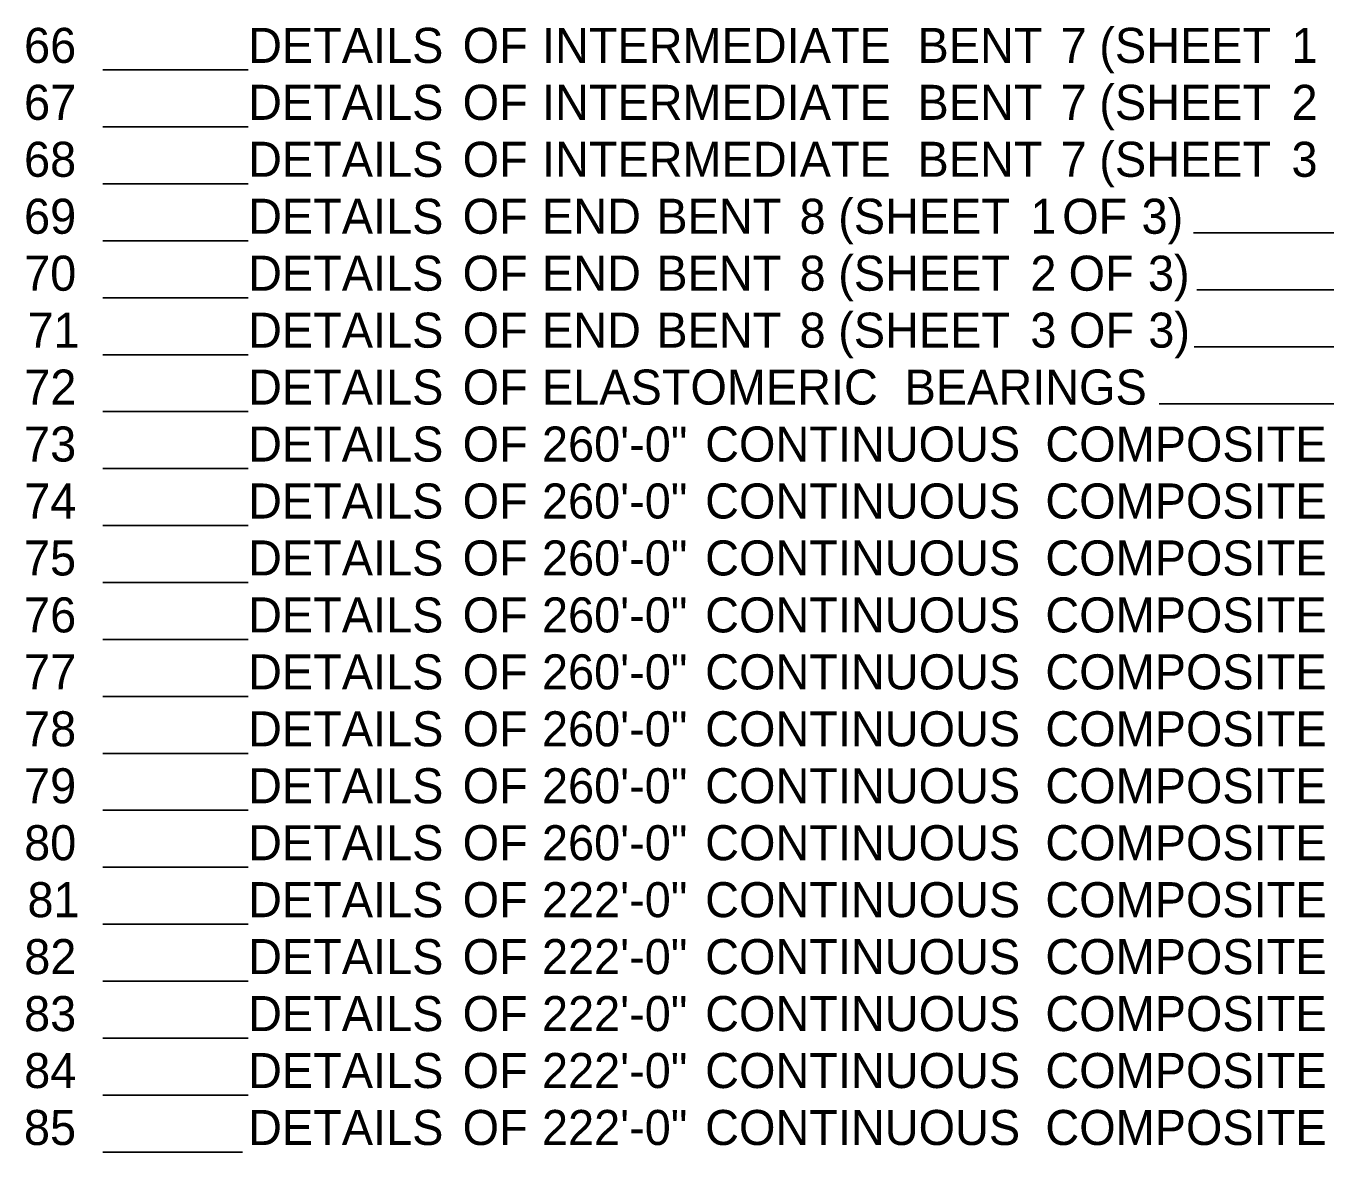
# Model space of a CAD drawing. Extents: x 2 to 32.9, y 0.7 to 21.4.
# Drawn here: x 2.74 to 8.57, y 6.11 to 11.17 of the extents above; entities that cross this region are included whole.
import ezdxf

# ---------------------------------------------------------------- set-up
doc = ezdxf.new("R2010")
doc.units = 0
doc.layers.add('Default', color=7, linetype='Continuous')

msp = doc.modelspace()

# ---------------------------------------------------------------- linework, layer by layer
at = {"layer": 'Default'}
for p, q in [((3.0822, 10.968), (3.734, 10.968)), ((3.0822, 10.968), (3.7084, 10.968)), ((3.0822, 10.968), (3.7084, 10.968)), ((3.0822, 10.7125), (3.734, 10.7125)), ((3.0822, 10.7125), (3.7084, 10.7125)), ((3.0822, 10.7125), (3.7084, 10.7125)), ((3.0822, 10.4569), (3.734, 10.4569)), ((3.0822, 10.4569), (3.7084, 10.4569)), ((3.0822, 10.4569), (3.7084, 10.4569)), ((7.9777, 10.2364), (13.6355, 10.2364)), ((3.0822, 10.2013), (3.734, 10.2013)), ((3.0822, 10.2013), (3.7084, 10.2013)), ((3.0822, 10.2013), (3.7084, 10.2013)), ((7.993, 9.9808), (13.6355, 9.9808)), ((3.0822, 9.9457), (3.734, 9.9457)), ((3.0822, 9.9457), (3.7084, 9.9457)), ((3.0822, 9.9457), (3.7084, 9.9457)), ((3.0822, 9.6901), (3.734, 9.6901)), ((3.0822, 9.6901), (3.7084, 9.6901)), ((3.0822, 9.6901), (3.7084, 9.6901)), ((7.9806, 9.7252), (13.6355, 9.7252)), ((7.8234, 9.4696), (13.6355, 9.4696)), ((3.0822, 9.4345), (3.734, 9.4345)), ((3.0822, 9.4345), (3.7084, 9.4345)), ((3.0822, 9.4345), (3.7084, 9.4345)), ((3.0822, 9.1789), (3.734, 9.1789)), ((3.0822, 9.1789), (3.7084, 9.1789)), ((3.0822, 9.1789), (3.7084, 9.1789)), ((3.0822, 8.9233), (3.734, 8.9233)), ((3.0822, 8.9233), (3.7084, 8.9233)), ((3.0822, 8.9233), (3.7084, 8.9233)), ((3.0822, 8.6677), (3.734, 8.6677)), ((3.0822, 8.6677), (3.7084, 8.6677)), ((3.0822, 8.6677), (3.7084, 8.6677)), ((3.0822, 8.4121), (3.734, 8.4121)), ((3.0822, 8.4121), (3.7084, 8.4121)), ((3.0822, 8.4121), (3.7084, 8.4121)), ((3.0822, 8.1565), (3.734, 8.1565)), ((3.0822, 8.1565), (3.7084, 8.1565)), ((3.0822, 8.1565), (3.7084, 8.1565)), ((3.0822, 7.901), (3.734, 7.901)), ((3.0822, 7.901), (3.7084, 7.901)), ((3.0822, 7.901), (3.7084, 7.901)), ((3.0822, 7.6454), (3.734, 7.6454)), ((3.0822, 7.6454), (3.7084, 7.6454)), ((3.0822, 7.6454), (3.7084, 7.6454)), ((3.0822, 7.3898), (3.734, 7.3898)), ((3.0822, 7.3898), (3.7084, 7.3898)), ((3.0822, 7.3898), (3.7084, 7.3898)), ((3.0822, 7.1342), (3.734, 7.1342)), ((3.0822, 7.1342), (3.7084, 7.1342)), ((3.0822, 7.1342), (3.7084, 7.1342)), ((3.0822, 6.8786), (3.734, 6.8786)), ((3.0822, 6.8786), (3.7084, 6.8786)), ((3.0822, 6.8786), (3.7084, 6.8786)), ((3.0822, 6.623), (3.734, 6.623)), ((3.0822, 6.623), (3.7084, 6.623)), ((3.0822, 6.623), (3.7084, 6.623)), ((3.0822, 6.3674), (3.734, 6.3674)), ((3.0822, 6.3674), (3.7084, 6.3674)), ((3.0822, 6.3674), (3.7084, 6.3674)), ((3.0822, 6.1118), (3.7084, 6.1118)), ((3.0822, 6.1118), (3.7084, 6.1118))]:
    msp.add_line(p, q, dxfattribs=at)

# ---------------------------------------------------------------- texts
for s, height, p in [('66', 0.15729, (2.7286, 10.9995)), ('66', 0.15729, (2.7286, 10.9995)), ('DETAILS', 0.15729, (3.734, 10.9995)), ('DETAILS', 0.15729, (3.734, 10.9995)), (' OF', 0.15729, (4.6385, 10.9995)), (' OF', 0.15729, (4.6385, 10.9995)), (' INTERMEDIATE', 0.157286, (4.9947, 10.9995)), (' INTERMEDIATE', 0.157286, (4.9947, 10.9995)), (' BENT', 0.15729, (6.6802, 10.9995)), (' BENT', 0.15729, (6.6802, 10.9995)), (' 7', 0.15729, (7.323, 10.9995)), (' 7', 0.15729, (7.323, 10.9995)), (' (SHEET', 0.15729, (7.4962, 10.9995)), (' (SHEET', 0.15729, (7.4962, 10.9995)), (' 1', 0.15729, (8.3588, 10.9995)), (' 1', 0.15729, (8.3588, 10.9995)), ('67', 0.15729, (2.7286, 10.7439)), ('67', 0.15729, (2.7286, 10.7439)), ('DETAILS', 0.15729, (3.734, 10.7439)), ('DETAILS', 0.15729, (3.734, 10.7439)), (' OF', 0.15729, (4.6385, 10.7439)), (' OF', 0.15729, (4.6385, 10.7439)), (' (SHEET', 0.15729, (7.4962, 10.7439)), (' (SHEET', 0.15729, (7.4962, 10.7439)), (' 2', 0.15729, (8.3588, 10.7439)), (' 2', 0.15729, (8.3588, 10.7439)), (' INTERMEDIATE', 0.157286, (4.9947, 10.7439)), (' INTERMEDIATE', 0.157286, (4.9947, 10.7439)), (' BENT', 0.15729, (6.6802, 10.7439)), (' BENT', 0.15729, (6.6802, 10.7439)), (' 7', 0.15729, (7.323, 10.7439)), (' 7', 0.15729, (7.323, 10.7439)), ('68', 0.15729, (2.7285, 10.4883)), ('68', 0.15729, (2.7285, 10.4883)), ('DETAILS', 0.15729, (3.734, 10.4883)), ('DETAILS', 0.15729, (3.734, 10.4883)), (' OF', 0.15729, (4.6385, 10.4883)), (' OF', 0.15729, (4.6385, 10.4883)), (' INTERMEDIATE', 0.157286, (4.9947, 10.4883)), (' INTERMEDIATE', 0.157286, (4.9947, 10.4883)), (' BENT', 0.15729, (6.6802, 10.4883)), (' BENT', 0.15729, (6.6802, 10.4883)), (' 7', 0.15729, (7.323, 10.4883)), (' 7', 0.15729, (7.323, 10.4883)), (' (SHEET', 0.15729, (7.4962, 10.4883)), (' (SHEET', 0.15729, (7.4962, 10.4883)), (' 3', 0.15729, (8.3588, 10.4883)), (' 3', 0.15729, (8.3588, 10.4883)), ('69', 0.15729, (2.7285, 10.2327)), ('69', 0.15729, (2.7285, 10.2327)), ('DETAILS', 0.15729, (3.734, 10.2327)), ('DETAILS', 0.15729, (3.734, 10.2327)), (' OF', 0.15729, (4.6385, 10.2327)), (' OF', 0.15729, (4.6385, 10.2327)), (' END', 0.15729, (4.9947, 10.2327)), (' END', 0.15729, (4.9947, 10.2327)), (' BENT', 0.15729, (5.508, 10.2327)), (' BENT', 0.15729, (5.508, 10.2327)), (' 8', 0.15729, (6.1508, 10.2327)), (' 8', 0.15729, (6.1508, 10.2327)), (' (SHEET', 0.15729, (6.3243, 10.2327)), (' (SHEET', 0.15729, (6.3243, 10.2327)), (' 1', 0.15729, (7.1868, 10.2327)), (' 1', 0.15729, (7.1868, 10.2327)), (' OF', 0.15729, (7.3296, 10.2327)), (' OF', 0.15729, (7.3296, 10.2327)), (' 3)', 0.15729, (7.6858, 10.2327)), (' 3)', 0.15729, (7.6858, 10.2327)), ('70', 0.15729, (2.7289, 9.9771)), ('70', 0.15729, (2.7289, 9.9771)), ('DETAILS', 0.15729, (3.734, 9.9771)), ('DETAILS', 0.15729, (3.734, 9.9771)), (' OF', 0.15729, (4.6385, 9.9771)), (' OF', 0.15729, (4.6385, 9.9771)), (' END', 0.15729, (4.9947, 9.9771)), (' END', 0.15729, (4.9947, 9.9771)), (' BENT', 0.15729, (5.508, 9.9771)), (' BENT', 0.15729, (5.508, 9.9771)), (' 8', 0.15729, (6.1508, 9.9771)), (' 8', 0.15729, (6.1508, 9.9771)), (' (SHEET', 0.15729, (6.3243, 9.9771)), (' (SHEET', 0.15729, (6.3243, 9.9771)), (' 2', 0.15729, (7.1868, 9.9771)), (' 2', 0.15729, (7.1868, 9.9771)), (' OF', 0.15729, (7.3584, 9.9771)), (' OF', 0.15729, (7.3584, 9.9771)), (' 3)', 0.15729, (7.7146, 9.9771)), (' 3)', 0.15729, (7.7146, 9.9771)), ('71', 0.15729, (2.7438, 9.7215)), ('71', 0.15729, (2.7438, 9.7215)), ('DETAILS', 0.15729, (3.734, 9.7215)), ('DETAILS', 0.15729, (3.734, 9.7215)), (' OF', 0.15729, (4.6385, 9.7215)), (' OF', 0.15729, (4.6385, 9.7215)), (' END', 0.15729, (4.9947, 9.7215)), (' END', 0.15729, (4.9947, 9.7215)), (' BENT', 0.15729, (5.508, 9.7215)), (' BENT', 0.15729, (5.508, 9.7215)), (' 8', 0.15729, (6.1508, 9.7215)), (' 8', 0.15729, (6.1508, 9.7215)), (' (SHEET', 0.15729, (6.3243, 9.7215)), (' (SHEET', 0.15729, (6.3243, 9.7215)), (' 3', 0.15729, (7.1868, 9.7215)), (' 3', 0.15729, (7.1868, 9.7215)), (' OF', 0.15729, (7.3601, 9.7215)), (' OF', 0.15729, (7.3601, 9.7215)), (' 3)', 0.15729, (7.7162, 9.7215)), (' 3)', 0.15729, (7.7162, 9.7215)), ('72', 0.15729, (2.7294, 9.466)), ('72', 0.15729, (2.7294, 9.466)), ('DETAILS', 0.15729, (3.734, 9.466)), ('DETAILS', 0.15729, (3.734, 9.466)), (' OF', 0.15729, (4.6385, 9.466)), (' OF', 0.15729, (4.6385, 9.466)), (' ELASTOMERIC', 0.157286, (4.9947, 9.466)), (' ELASTOMERIC', 0.157286, (4.9947, 9.466)), (' BEARINGS', 0.15729, (6.6223, 9.466)), (' BEARINGS', 0.15729, (6.6223, 9.466)), ('73', 0.15729, (2.7286, 9.2104)), ('73', 0.15729, (2.7286, 9.2104)), ('DETAILS', 0.15729, (3.734, 9.2104)), ('DETAILS', 0.15729, (3.734, 9.2104)), (' OF', 0.15729, (4.6385, 9.2104)), (' OF', 0.15729, (4.6385, 9.2104)), (' 260\'-0"', 0.15729, (4.9947, 9.2104)), (' 260\'-0"', 0.15729, (4.9947, 9.2104)), (' CONTINUOUS', 0.157286, (5.7271, 9.2104)), (' CONTINUOUS', 0.157286, (5.7271, 9.2104)), (' COMPOSITE', 0.15729, (7.2541, 9.2104)), (' COMPOSITE', 0.15729, (7.2541, 9.2104)), ('74', 0.15729, (2.729, 8.9548)), ('74', 0.15729, (2.729, 8.9548)), ('DETAILS', 0.15729, (3.734, 8.9548)), ('DETAILS', 0.15729, (3.734, 8.9548)), (' OF', 0.15729, (4.6385, 8.9548)), (' OF', 0.15729, (4.6385, 8.9548)), (' 260\'-0"', 0.15729, (4.9947, 8.9548)), (' 260\'-0"', 0.15729, (4.9947, 8.9548)), (' CONTINUOUS', 0.157286, (5.7271, 8.9548)), (' CONTINUOUS', 0.157286, (5.7271, 8.9548)), (' COMPOSITE', 0.15729, (7.2541, 8.9548)), (' COMPOSITE', 0.15729, (7.2541, 8.9548)), ('75', 0.15729, (2.728, 8.6992)), ('75', 0.15729, (2.728, 8.6992)), ('DETAILS', 0.15729, (3.734, 8.6992)), ('DETAILS', 0.15729, (3.734, 8.6992)), (' OF', 0.15729, (4.6385, 8.6992)), (' OF', 0.15729, (4.6385, 8.6992)), (' 260\'-0"', 0.15729, (4.9947, 8.6992)), (' 260\'-0"', 0.15729, (4.9947, 8.6992)), (' CONTINUOUS', 0.157286, (5.7271, 8.6992)), (' CONTINUOUS', 0.157286, (5.7271, 8.6992)), (' COMPOSITE', 0.15729, (7.2541, 8.6992)), (' COMPOSITE', 0.15729, (7.2541, 8.6992)), ('76', 0.15729, (2.7286, 8.4436)), ('76', 0.15729, (2.7286, 8.4436)), ('DETAILS', 0.15729, (3.734, 8.4436)), ('DETAILS', 0.15729, (3.734, 8.4436)), (' OF', 0.15729, (4.6385, 8.4436)), (' OF', 0.15729, (4.6385, 8.4436)), (' 260\'-0"', 0.15729, (4.9947, 8.4436)), (' 260\'-0"', 0.15729, (4.9947, 8.4436)), (' CONTINUOUS', 0.157286, (5.7271, 8.4436)), (' CONTINUOUS', 0.157286, (5.7271, 8.4436)), (' COMPOSITE', 0.15729, (7.2541, 8.4436)), (' COMPOSITE', 0.15729, (7.2541, 8.4436)), ('77', 0.15729, (2.7286, 8.188)), ('77', 0.15729, (2.7286, 8.188)), ('DETAILS', 0.15729, (3.734, 8.188)), ('DETAILS', 0.15729, (3.734, 8.188)), (' OF', 0.15729, (4.6385, 8.188)), (' OF', 0.15729, (4.6385, 8.188)), (' 260\'-0"', 0.15729, (4.9947, 8.188)), (' 260\'-0"', 0.15729, (4.9947, 8.188)), (' CONTINUOUS', 0.157286, (5.7271, 8.188)), (' CONTINUOUS', 0.157286, (5.7271, 8.188)), (' COMPOSITE', 0.15729, (7.2541, 8.188)), (' COMPOSITE', 0.15729, (7.2541, 8.188)), ('78', 0.15729, (2.7285, 7.9324)), ('78', 0.15729, (2.7285, 7.9324)), ('DETAILS', 0.15729, (3.734, 7.9324)), ('DETAILS', 0.15729, (3.734, 7.9324)), (' OF', 0.15729, (4.6385, 7.9324)), (' OF', 0.15729, (4.6385, 7.9324)), (' 260\'-0"', 0.15729, (4.9947, 7.9324)), (' 260\'-0"', 0.15729, (4.9947, 7.9324)), (' CONTINUOUS', 0.157286, (5.7271, 7.9324)), (' CONTINUOUS', 0.157286, (5.7271, 7.9324)), (' COMPOSITE', 0.15729, (7.2541, 7.9324)), (' COMPOSITE', 0.15729, (7.2541, 7.9324)), ('79', 0.15729, (2.7285, 7.6768)), ('79', 0.15729, (2.7285, 7.6768)), ('DETAILS', 0.15729, (3.734, 7.6768)), ('DETAILS', 0.15729, (3.734, 7.6768)), (' OF', 0.15729, (4.6385, 7.6768)), (' OF', 0.15729, (4.6385, 7.6768)), (' 260\'-0"', 0.15729, (4.9947, 7.6768)), (' 260\'-0"', 0.15729, (4.9947, 7.6768)), (' CONTINUOUS', 0.157286, (5.7271, 7.6768)), (' CONTINUOUS', 0.157286, (5.7271, 7.6768)), (' COMPOSITE', 0.15729, (7.2541, 7.6768)), (' COMPOSITE', 0.15729, (7.2541, 7.6768)), ('80', 0.15729, (2.7289, 7.4212)), ('80', 0.15729, (2.7289, 7.4212)), ('DETAILS', 0.15729, (3.734, 7.4212)), ('DETAILS', 0.15729, (3.734, 7.4212)), (' OF', 0.15729, (4.6385, 7.4212)), (' OF', 0.15729, (4.6385, 7.4212)), (' 260\'-0"', 0.15729, (4.9947, 7.4212)), (' 260\'-0"', 0.15729, (4.9947, 7.4212)), (' CONTINUOUS', 0.157286, (5.7271, 7.4212)), (' CONTINUOUS', 0.157286, (5.7271, 7.4212)), (' COMPOSITE', 0.15729, (7.2541, 7.4212)), (' COMPOSITE', 0.15729, (7.2541, 7.4212)), ('81', 0.15729, (2.7438, 7.1656)), ('81', 0.15729, (2.7438, 7.1656)), ('DETAILS', 0.15729, (3.734, 7.1656)), ('DETAILS', 0.15729, (3.734, 7.1656)), (' OF', 0.15729, (4.6385, 7.1656)), (' OF', 0.15729, (4.6385, 7.1656)), (' 222\'-0"', 0.15729, (4.9947, 7.1656)), (' 222\'-0"', 0.15729, (4.9947, 7.1656)), (' CONTINUOUS', 0.157286, (5.7271, 7.1656)), (' CONTINUOUS', 0.157286, (5.7271, 7.1656)), (' COMPOSITE', 0.15729, (7.2541, 7.1656)), (' COMPOSITE', 0.15729, (7.2541, 7.1656)), ('82', 0.15729, (2.7294, 6.9101)), ('82', 0.15729, (2.7294, 6.9101)), ('DETAILS', 0.15729, (3.734, 6.9101)), ('DETAILS', 0.15729, (3.734, 6.9101)), (' OF', 0.15729, (4.6385, 6.9101)), (' OF', 0.15729, (4.6385, 6.9101)), (' 222\'-0"', 0.15729, (4.9947, 6.9101)), (' 222\'-0"', 0.15729, (4.9947, 6.9101)), (' CONTINUOUS', 0.157286, (5.7271, 6.9101)), (' CONTINUOUS', 0.157286, (5.7271, 6.9101)), (' COMPOSITE', 0.15729, (7.2541, 6.9101)), (' COMPOSITE', 0.15729, (7.2541, 6.9101)), ('83', 0.15729, (2.7286, 6.6545)), ('83', 0.15729, (2.7286, 6.6545)), ('DETAILS', 0.15729, (3.734, 6.6545)), ('DETAILS', 0.15729, (3.734, 6.6545)), (' OF', 0.15729, (4.6385, 6.6545)), (' OF', 0.15729, (4.6385, 6.6545)), (' 222\'-0"', 0.15729, (4.9947, 6.6545)), (' 222\'-0"', 0.15729, (4.9947, 6.6545)), (' CONTINUOUS', 0.157286, (5.7271, 6.6545)), (' CONTINUOUS', 0.157286, (5.7271, 6.6545)), (' COMPOSITE', 0.15729, (7.2541, 6.6545)), (' COMPOSITE', 0.15729, (7.2541, 6.6545)), ('84', 0.15729, (2.729, 6.3989)), ('84', 0.15729, (2.729, 6.3989)), ('DETAILS', 0.15729, (3.734, 6.3989)), ('DETAILS', 0.15729, (3.734, 6.3989)), (' OF', 0.15729, (4.6385, 6.3989)), (' OF', 0.15729, (4.6385, 6.3989)), (' 222\'-0"', 0.15729, (4.9947, 6.3989)), (' 222\'-0"', 0.15729, (4.9947, 6.3989)), (' CONTINUOUS', 0.157286, (5.7271, 6.3989)), (' CONTINUOUS', 0.157286, (5.7271, 6.3989)), (' COMPOSITE', 0.15729, (7.2541, 6.3989)), (' COMPOSITE', 0.15729, (7.2541, 6.3989)), ('85', 0.15729, (2.728, 6.1433)), ('85', 0.15729, (2.728, 6.1433)), ('DETAILS', 0.15729, (3.734, 6.1433)), ('DETAILS', 0.15729, (3.734, 6.1433)), (' OF', 0.15729, (4.6385, 6.1433)), (' OF', 0.15729, (4.6385, 6.1433)), (' 222\'-0"', 0.15729, (4.9947, 6.1433)), (' 222\'-0"', 0.15729, (4.9947, 6.1433)), (' CONTINUOUS', 0.157286, (5.7271, 6.1433)), (' CONTINUOUS', 0.157286, (5.7271, 6.1433)), (' COMPOSITE', 0.15729, (7.2541, 6.1433)), (' COMPOSITE', 0.15729, (7.2541, 6.1433))]:
    msp.add_text(s, height=height, dxfattribs=at).set_placement(p)

doc.saveas('drawing.dxf')
